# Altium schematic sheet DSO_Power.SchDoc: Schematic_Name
size A4; CompanyName: University of Melbourne; Engineer: Your Name Here; DocumentNumber: 1; Revision: 0.1; SheetNumber: 1; SheetTotal: 1; Title_Project: Project_Title; StudentNo: Student No.
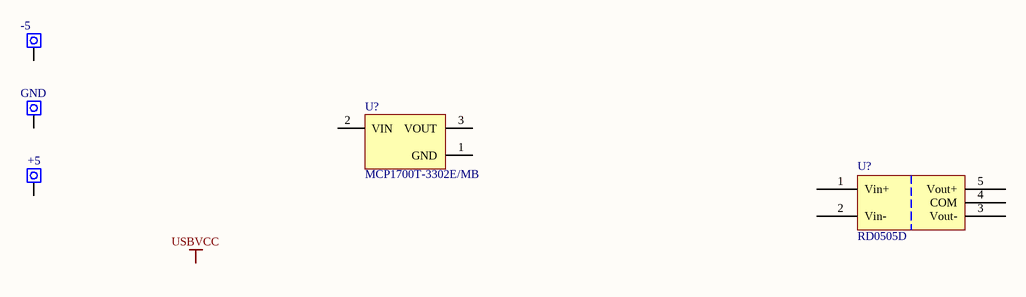
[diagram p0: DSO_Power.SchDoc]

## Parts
(Parts that share a designator on the sheet are numbered #1, #2 ... from top to bottom, then left to right.)
TP?#1  -5  [PIN 1.8mm]
TP?#2  GND  [PIN 1.8mm]
TP?#3  +5  [PIN 1.8mm]
U?#1  MCP1700T-3302E/MB  [SOT89]
U?#2  RD0505D  [SIP_NMG]

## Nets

Not connected (* = marked no-connect by the designer): TP?#1 1; TP?#2 1; TP?#3 1; U?#1 1(GND) 2(VIN) 3(VOUT); U?#2 1(Vin+) 2(Vin-) 3(Vout-) 4(COM) 5(Vout+)

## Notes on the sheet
- Labels drawn without touching a wire or pin: USBVCC

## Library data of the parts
TP?#1-TP?#3 = WIRE: Pad
U?#1 = MCP1700T: Low Quiescent Current LDO, 3-Pin SOT-89, Extended Temperature, Tape and Reel; Reviewed by: RM - 2018/08/05
U?#2 = RD0505D: (ADV) DC to DC converter 5V in +-5V out; Reviewed by: RM - 2018/08/05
